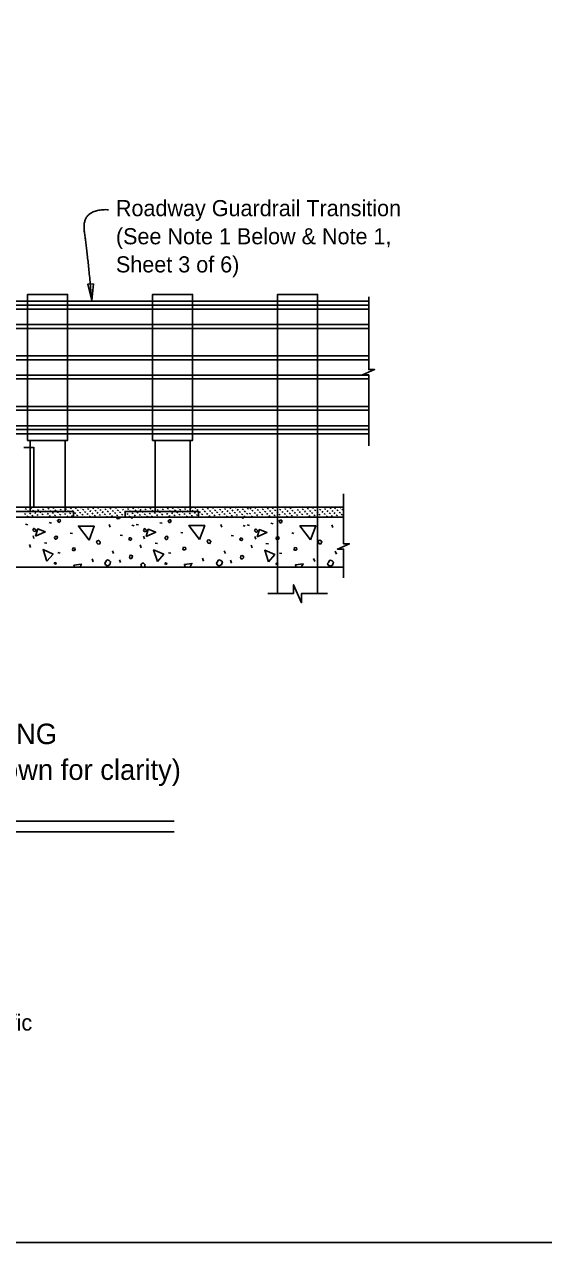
# Model space of a CAD drawing. Extents: x 1.5 to 68.7, y 0 to 31.1.
# Drawn here: x 14.15 to 20.65, y 1.78 to 17.03 of the extents above; entities that cross this region are included whole.
import ezdxf

# ---------------------------------------------------------------- set-up
doc = ezdxf.new("R2010")
doc.units = 0
for name, color, linetype in [('ActivePts-ConstElements', 7, 'Continuous'), ('Dimension', 7, 'Continuous'), ('Miscellaneous', 7, 'Continuous'), ('TrafBarrierConc', 7, 'Continuous')]:
    doc.layers.add(name, color=color, linetype=linetype)

msp = doc.modelspace()

# ---------------------------------------------------------------- linework, layer by layer
at = {"layer": 'ActivePts-ConstElements'}
msp.add_lwpolyline([(1.467, 28.183), (42.533, 28.183), (42.533, 1.783), (1.467, 1.783)], close=True, dxfattribs=at)
at = {"layer": 'Dimension'}
for p, q in [((12.038, 7.055), (16.027, 7.055)), ((12.038, 6.925), (16.027, 6.925))]:
    msp.add_line(p, q, dxfattribs=at)
msp.add_lwpolyline([(14.995, 13.57), (15.016, 13.78), (14.945, 13.775)], close=True, dxfattribs=at)
for points in [[(18.46, 11.755), (18.46, 12.641), (18.382, 12.641), (18.532, 12.708), (18.46, 12.708), (18.46, 13.616)], [(18.144, 10.101), (18.144, 10.462), (18.067, 10.462), (18.217, 10.528), (18.144, 10.528), (18.144, 11.154)], [(17.945, 9.906), (17.619, 9.906), (17.619, 9.789), (17.52, 10.014), (17.52, 9.906), (17.195, 9.906)]]:
    msp.add_lwpolyline(points, dxfattribs=at)
msp.add_open_spline([(15.206, 14.708), (14.861, 14.721), (14.944, 14.148), (14.995, 13.57)], degree=2, dxfattribs=at)
at = {"layer": 'Miscellaneous'}
for p, q in [((6.514, 13.565), (18.46, 13.565)), ((7.172, 13.512), (18.46, 13.512)), ((7.173, 13.464), (18.46, 13.464)), ((7.178, 13.271), (18.46, 13.271)), ((7.179, 13.223), (18.46, 13.223)), ((7.174, 12.831), (18.46, 12.831)), ((7.175, 12.879), (18.46, 12.879)), ((7.168, 12.59), (18.46, 12.59)), ((7.169, 12.638), (18.46, 12.638)), ((7.178, 12.198), (18.46, 12.198)), ((7.179, 12.246), (18.46, 12.246)), ((6.514, 11.904), (18.46, 11.904)), ((7.172, 11.957), (18.46, 11.957)), ((7.173, 12.005), (18.46, 12.005)), ((14.224, 10.932), (14.224, 11.821)), ((14.662, 10.932), (14.662, 11.821)), ((15.787, 10.932), (15.787, 11.821)), ((16.224, 10.932), (16.224, 11.821)), ((14.229, 10.963), (14.238, 10.977)), ((14.511, 10.968), (14.519, 10.982)), ((14.729, 10.965), (14.737, 10.979)), ((14.79, 10.967), (14.798, 10.981)), ((14.854, 10.975), (14.859, 10.985)), ((14.917, 10.983), (14.918, 10.985)), ((15.009, 10.963), (15.017, 10.977)), ((15.072, 10.971), (15.08, 10.985)), ((15.136, 10.98), (15.138, 10.985)), ((15.29, 10.968), (15.298, 10.982)), ((15.354, 10.976), (15.359, 10.985)), ((15.417, 10.984), (15.417, 10.985)), ((15.508, 10.965), (15.516, 10.979)), ((15.572, 10.973), (15.579, 10.985)), ((15.635, 10.981), (15.637, 10.985)), ((15.787, 10.97), (15.796, 10.984)), ((15.851, 10.978), (15.855, 10.985)), ((16.006, 10.967), (16.014, 10.981)), ((16.069, 10.975), (16.075, 10.985)), ((16.133, 10.983), (16.134, 10.985)), ((16.224, 10.963), (16.232, 10.977)), ((16.287, 10.971), (16.295, 10.985)), ((16.351, 10.98), (16.354, 10.985)), ((16.505, 10.968), (16.514, 10.982)), ((16.569, 10.976), (16.574, 10.985)), ((16.632, 10.984), (16.633, 10.985)), ((16.724, 10.965), (16.732, 10.979)), ((16.788, 10.973), (16.795, 10.984)), ((16.851, 10.981), (16.853, 10.984)), ((17.039, 10.97), (17.047, 10.984)), ((17.257, 10.967), (17.265, 10.981)), ((17.475, 10.963), (17.484, 10.977)), ((17.757, 10.968), (17.765, 10.982)), ((17.975, 10.965), (17.983, 10.979)), ((18.036, 10.967), (18.044, 10.981)), ((18.1, 10.975), (18.105, 10.985)), ((14.158, 10.892), (14.166, 10.906)), ((14.166, 10.955), (14.174, 10.969)), ((14.186, 10.864), (14.194, 10.878)), ((14.194, 10.928), (14.202, 10.942)), ((14.221, 10.9), (14.229, 10.914)), ((14.245, 10.859), (14.247, 10.862)), ((14.249, 10.872), (14.257, 10.886)), ((14.257, 10.936), (14.265, 10.95)), ((14.285, 10.908), (14.293, 10.922)), ((14.313, 10.88), (14.321, 10.894)), ((14.321, 10.944), (14.329, 10.958)), ((14.348, 10.916), (14.356, 10.93)), ((14.376, 10.888), (14.384, 10.902)), ((14.384, 10.952), (14.392, 10.966)), ((14.412, 10.924), (14.42, 10.938)), ((14.44, 10.896), (14.448, 10.91)), ((14.448, 10.96), (14.456, 10.974)), ((14.467, 10.869), (14.475, 10.883)), ((14.475, 10.932), (14.483, 10.946)), ((14.503, 10.905), (14.511, 10.919)), ((14.524, 10.859), (14.528, 10.867)), ((14.531, 10.877), (14.539, 10.891)), ((14.539, 10.94), (14.547, 10.954)), ((14.567, 10.913), (14.575, 10.927)), ((14.594, 10.885), (14.602, 10.899)), ((14.602, 10.948), (14.61, 10.962)), ((14.63, 10.921), (14.638, 10.935)), ((14.658, 10.893), (14.666, 10.907)), ((14.666, 10.957), (14.674, 10.971)), ((14.685, 10.865), (14.694, 10.879)), ((14.694, 10.929), (14.702, 10.943)), ((14.721, 10.901), (14.729, 10.915)), ((14.746, 10.867), (14.755, 10.881)), ((14.755, 10.931), (14.763, 10.945)), ((14.782, 10.903), (14.79, 10.917)), ((14.81, 10.876), (14.818, 10.89)), ((14.818, 10.939), (14.826, 10.953)), ((14.844, 10.86), (14.846, 10.862)), ((14.846, 10.911), (14.854, 10.925)), ((14.873, 10.884), (14.882, 10.898)), ((14.882, 10.947), (14.89, 10.961)), ((14.903, 10.86), (14.909, 10.87)), ((14.909, 10.919), (14.917, 10.933)), ((14.937, 10.892), (14.945, 10.906)), ((14.945, 10.955), (14.953, 10.969)), ((14.965, 10.864), (14.973, 10.878)), ((14.973, 10.928), (14.981, 10.942)), ((15, 10.9), (15.009, 10.914)), ((15.028, 10.872), (15.036, 10.886)), ((15.036, 10.936), (15.044, 10.95)), ((15.064, 10.908), (15.072, 10.922)), ((15.092, 10.88), (15.1, 10.894)), ((15.099, 10.856), (15.099, 10.856)), ((15.1, 10.944), (15.108, 10.958)), ((15.123, 10.86), (15.127, 10.867)), ((15.127, 10.916), (15.136, 10.93)), ((15.155, 10.888), (15.163, 10.902)), ((15.163, 10.952), (15.171, 10.966)), ((15.183, 10.861), (15.191, 10.875)), ((15.191, 10.924), (15.199, 10.938)), ((15.219, 10.896), (15.227, 10.91)), ((15.227, 10.96), (15.235, 10.974)), ((15.246, 10.869), (15.254, 10.883)), ((15.254, 10.932), (15.263, 10.946)), ((15.282, 10.905), (15.29, 10.919)), ((15.31, 10.877), (15.318, 10.891)), ((15.318, 10.94), (15.326, 10.954)), ((15.343, 10.86), (15.346, 10.863)), ((15.346, 10.913), (15.354, 10.927)), ((15.373, 10.885), (15.381, 10.899)), ((15.381, 10.948), (15.39, 10.962)), ((15.402, 10.86), (15.409, 10.871)), ((15.409, 10.921), (15.417, 10.935)), ((15.437, 10.893), (15.445, 10.907)), ((15.445, 10.957), (15.453, 10.971)), ((15.464, 10.865), (15.473, 10.879)), ((15.473, 10.929), (15.481, 10.943)), ((15.5, 10.901), (15.508, 10.915)), ((15.528, 10.874), (15.536, 10.888)), ((15.536, 10.937), (15.544, 10.951)), ((15.564, 10.909), (15.572, 10.923)), ((15.564, 10.86), (15.564, 10.86)), ((15.591, 10.882), (15.6, 10.896)), ((15.6, 10.945), (15.608, 10.959)), ((15.622, 10.86), (15.627, 10.868)), ((15.627, 10.917), (15.635, 10.931)), ((15.655, 10.89), (15.663, 10.904)), ((15.663, 10.953), (15.671, 10.967)), ((15.683, 10.862), (15.691, 10.876)), ((15.691, 10.926), (15.699, 10.94)), ((15.718, 10.898), (15.727, 10.912)), ((15.727, 10.961), (15.735, 10.975)), ((15.746, 10.87), (15.751, 10.879)), ((15.752, 10.934), (15.76, 10.948)), ((15.779, 10.907), (15.787, 10.921)), ((15.807, 10.879), (15.815, 10.893)), ((15.815, 10.942), (15.823, 10.956)), ((15.843, 10.915), (15.851, 10.929)), ((15.871, 10.887), (15.879, 10.901)), ((15.879, 10.951), (15.887, 10.965)), ((15.906, 10.923), (15.914, 10.937)), ((15.934, 10.895), (15.942, 10.909)), ((15.942, 10.959), (15.95, 10.973)), ((15.962, 10.867), (15.97, 10.881)), ((15.97, 10.931), (15.978, 10.945)), ((15.998, 10.903), (16.006, 10.917)), ((16.025, 10.876), (16.033, 10.89)), ((16.033, 10.939), (16.041, 10.953)), ((16.061, 10.911), (16.069, 10.925)), ((16.089, 10.884), (16.097, 10.898)), ((16.097, 10.947), (16.105, 10.961)), ((16.125, 10.919), (16.133, 10.933)), ((16.152, 10.892), (16.16, 10.906)), ((16.16, 10.955), (16.168, 10.969)), ((16.18, 10.864), (16.188, 10.878)), ((16.188, 10.928), (16.196, 10.942)), ((16.216, 10.9), (16.224, 10.914)), ((16.239, 10.86), (16.241, 10.862)), ((16.243, 10.872), (16.252, 10.886)), ((16.252, 10.936), (16.26, 10.95)), ((16.279, 10.908), (16.287, 10.922)), ((16.307, 10.88), (16.315, 10.894)), ((16.315, 10.944), (16.323, 10.958)), ((16.343, 10.916), (16.351, 10.93)), ((16.37, 10.888), (16.378, 10.902)), ((16.378, 10.952), (16.387, 10.966)), ((16.406, 10.924), (16.414, 10.938)), ((16.434, 10.896), (16.442, 10.91)), ((16.442, 10.96), (16.45, 10.974)), ((16.462, 10.869), (16.47, 10.883)), ((16.47, 10.932), (16.478, 10.946)), ((16.497, 10.905), (16.505, 10.919)), ((16.518, 10.86), (16.523, 10.867)), ((16.525, 10.877), (16.533, 10.891)), ((16.533, 10.94), (16.541, 10.954)), ((16.561, 10.913), (16.569, 10.927)), ((16.589, 10.885), (16.597, 10.899)), ((16.597, 10.948), (16.605, 10.962)), ((16.624, 10.921), (16.632, 10.935)), ((16.652, 10.893), (16.66, 10.907)), ((16.66, 10.957), (16.668, 10.971)), ((16.68, 10.865), (16.688, 10.879)), ((16.688, 10.929), (16.696, 10.943)), ((16.716, 10.901), (16.724, 10.915)), ((16.739, 10.859), (16.741, 10.863)), ((16.744, 10.873), (16.752, 10.887)), ((16.752, 10.937), (16.76, 10.951)), ((16.78, 10.909), (16.788, 10.923)), ((16.798, 10.859), (16.805, 10.871)), ((16.807, 10.882), (16.815, 10.896)), ((16.815, 10.945), (16.824, 10.959)), ((16.843, 10.917), (16.851, 10.931)), ((16.871, 10.89), (16.879, 10.904)), ((16.879, 10.953), (16.887, 10.967)), ((16.899, 10.862), (16.907, 10.876)), ((16.907, 10.925), (16.915, 10.939)), ((16.934, 10.898), (16.942, 10.912)), ((16.942, 10.961), (16.951, 10.975)), ((16.953, 10.855), (16.953, 10.855)), ((16.97, 10.898), (16.978, 10.912)), ((16.978, 10.961), (16.986, 10.975)), ((16.998, 10.87), (17.003, 10.879)), ((17.003, 10.934), (17.011, 10.948)), ((17.031, 10.907), (17.039, 10.921)), ((17.059, 10.879), (17.067, 10.893)), ((17.067, 10.942), (17.075, 10.956)), ((17.095, 10.915), (17.103, 10.929)), ((17.122, 10.887), (17.13, 10.901)), ((17.13, 10.951), (17.138, 10.964)), ((17.158, 10.923), (17.166, 10.937)), ((17.186, 10.895), (17.194, 10.909)), ((17.194, 10.959), (17.202, 10.973)), ((17.213, 10.867), (17.221, 10.881)), ((17.221, 10.931), (17.23, 10.945)), ((17.249, 10.903), (17.257, 10.917)), ((17.277, 10.876), (17.285, 10.89)), ((17.285, 10.939), (17.293, 10.953)), ((17.313, 10.911), (17.321, 10.925)), ((17.34, 10.884), (17.348, 10.898)), ((17.348, 10.947), (17.357, 10.961)), ((17.376, 10.919), (17.384, 10.933)), ((17.404, 10.892), (17.412, 10.906)), ((17.412, 10.955), (17.42, 10.969)), ((17.432, 10.864), (17.44, 10.878)), ((17.44, 10.928), (17.448, 10.942)), ((17.467, 10.9), (17.475, 10.914)), ((17.491, 10.859), (17.492, 10.862)), ((17.495, 10.872), (17.503, 10.886)), ((17.503, 10.936), (17.511, 10.95)), ((17.531, 10.908), (17.539, 10.922)), ((17.559, 10.88), (17.567, 10.894)), ((17.567, 10.944), (17.575, 10.958)), ((17.594, 10.916), (17.602, 10.93)), ((17.622, 10.888), (17.63, 10.902)), ((17.63, 10.952), (17.638, 10.966)), ((17.658, 10.924), (17.666, 10.938)), ((17.686, 10.896), (17.694, 10.91)), ((17.694, 10.96), (17.702, 10.974)), ((17.713, 10.869), (17.721, 10.883)), ((17.721, 10.932), (17.729, 10.946)), ((17.749, 10.905), (17.757, 10.919)), ((17.77, 10.859), (17.774, 10.867)), ((17.777, 10.877), (17.785, 10.891)), ((17.785, 10.94), (17.793, 10.954)), ((17.813, 10.913), (17.821, 10.927)), ((17.84, 10.885), (17.848, 10.899)), ((17.848, 10.948), (17.856, 10.962)), ((17.876, 10.921), (17.884, 10.935)), ((17.904, 10.893), (17.912, 10.907)), ((17.912, 10.957), (17.92, 10.971)), ((17.931, 10.865), (17.94, 10.879)), ((17.94, 10.929), (17.948, 10.943)), ((17.967, 10.901), (17.975, 10.915)), ((17.992, 10.867), (18.001, 10.881)), ((18.001, 10.931), (18.009, 10.945)), ((18.028, 10.903), (18.036, 10.917)), ((18.056, 10.876), (18.064, 10.89)), ((18.064, 10.939), (18.072, 10.953)), ((18.09, 10.86), (18.092, 10.862)), ((18.092, 10.911), (18.1, 10.925)), ((18.119, 10.884), (18.128, 10.898)), ((18.128, 10.947), (18.136, 10.961)), ((14.166, 10.773), (14.195, 10.766)), ((14.462, 10.792), (14.492, 10.787)), ((15.224, 10.734), (15.212, 10.768)), ((15.498, 10.761), (15.527, 10.754)), ((15.55, 10.77), (15.578, 10.763)), ((15.846, 10.789), (15.876, 10.784)), ((16.621, 10.734), (16.609, 10.768)), ((16.887, 10.756), (16.915, 10.749)), ((16.939, 10.765), (16.967, 10.758)), ((17.235, 10.784), (17.265, 10.779)), ((18.01, 10.73), (17.998, 10.763)), ((14.272, 10.592), (14.26, 10.626)), ((14.402, 10.538), (14.434, 10.534)), ((14.726, 10.66), (14.752, 10.655)), ((15.352, 10.635), (15.378, 10.63)), ((15.656, 10.589), (15.644, 10.622)), ((15.786, 10.534), (15.817, 10.531)), ((16.108, 10.668), (16.135, 10.663)), ((16.74, 10.631), (16.767, 10.625)), ((17.045, 10.584), (17.033, 10.618)), ((17.174, 10.53), (17.206, 10.526)), ((17.497, 10.664), (17.524, 10.658)), ((14.23, 10.483), (14.216, 10.518)), ((14.57, 10.419), (14.598, 10.412)), ((15.268, 10.404), (15.254, 10.439)), ((15.614, 10.479), (15.599, 10.514)), ((15.953, 10.416), (15.982, 10.409)), ((16.666, 10.404), (16.651, 10.439)), ((17.003, 10.475), (16.988, 10.51)), ((17.342, 10.411), (17.371, 10.404)), ((18.054, 10.399), (18.04, 10.434)), ((15.012, 10.303), (14.998, 10.338)), ((15.356, 10.292), (15.341, 10.327)), ((16.394, 10.311), (16.38, 10.346)), ((16.744, 10.287), (16.73, 10.323)), ((17.783, 10.307), (17.769, 10.342))]:
    msp.add_line(p, q, dxfattribs=at)
for points in [[(14.193, 11.821), (14.693, 11.821), (14.693, 13.648), (14.193, 13.648)], [(15.755, 11.821), (16.255, 11.821), (16.255, 13.648), (15.755, 13.648)], [(13.85, 10.859), (14.766, 10.859), (14.766, 10.932), (13.85, 10.932)], [(15.412, 10.859), (16.329, 10.859), (16.329, 10.932), (15.412, 10.932)]]:
    msp.add_lwpolyline(points, close=True, dxfattribs=at)
for points in [[(17.32, 9.906), (17.32, 13.648), (17.82, 13.648), (17.82, 9.906)], [(14.573, 10.805), (14.584, 10.794), (14.595, 10.801), (14.602, 10.812), (14.598, 10.829), (14.589, 10.831), (14.577, 10.829), (14.566, 10.819), (14.573, 10.805)], [(15.306, 10.856), (15.316, 10.84), (15.339, 10.842), (15.348, 10.851), (15.353, 10.856)], [(15.495, 10.846), (15.492, 10.856)], [(15.5, 10.856), (15.495, 10.846)], [(15.957, 10.801), (15.968, 10.791), (15.978, 10.798), (15.985, 10.808), (15.982, 10.826), (15.973, 10.828), (15.961, 10.826), (15.95, 10.815), (15.957, 10.801)], [(16.884, 10.842), (16.881, 10.852)], [(16.889, 10.852), (16.884, 10.842)], [(14.269, 10.685), (14.281, 10.683), (14.294, 10.688), (14.297, 10.699), (14.292, 10.708), (14.281, 10.715), (14.269, 10.72), (14.262, 10.706), (14.258, 10.696), (14.269, 10.685)], [(14.291, 10.621), (14.319, 10.713), (14.413, 10.676), (14.291, 10.621)], [(14.961, 10.573), (14.827, 10.75), (15.026, 10.748), (14.961, 10.573)], [(15.652, 10.681), (15.665, 10.68), (15.677, 10.685), (15.681, 10.696), (15.675, 10.704), (15.665, 10.712), (15.652, 10.717), (15.645, 10.703), (15.642, 10.692), (15.652, 10.681)], [(15.674, 10.617), (15.702, 10.709), (15.796, 10.672), (15.674, 10.617)], [(16.343, 10.581), (16.209, 10.758), (16.409, 10.756), (16.343, 10.581)], [(17.041, 10.677), (17.054, 10.675), (17.066, 10.681), (17.07, 10.691), (17.064, 10.7), (17.054, 10.707), (17.041, 10.712), (17.034, 10.698), (17.031, 10.688), (17.041, 10.677)], [(17.063, 10.613), (17.091, 10.705), (17.185, 10.668), (17.063, 10.613)], [(17.346, 10.797), (17.357, 10.786), (17.367, 10.793), (17.374, 10.804), (17.371, 10.822), (17.362, 10.823), (17.349, 10.822), (17.339, 10.811), (17.346, 10.797)], [(17.732, 10.577), (17.598, 10.754), (17.798, 10.752), (17.732, 10.577)], [(14.538, 10.585), (14.545, 10.585), (14.559, 10.593), (14.565, 10.608), (14.563, 10.617), (14.549, 10.624), (14.531, 10.614), (14.527, 10.603), (14.531, 10.593), (14.538, 10.585)], [(15.06, 10.541), (15.069, 10.525), (15.09, 10.522), (15.099, 10.538), (15.102, 10.552), (15.093, 10.561), (15.078, 10.57), (15.062, 10.564), (15.056, 10.548), (15.06, 10.541)], [(15.459, 10.577), (15.479, 10.571), (15.491, 10.58), (15.493, 10.593), (15.489, 10.596), (15.475, 10.603), (15.463, 10.601), (15.461, 10.589), (15.459, 10.577)], [(15.922, 10.582), (15.929, 10.582), (15.943, 10.589), (15.948, 10.605), (15.946, 10.614), (15.932, 10.621), (15.915, 10.61), (15.911, 10.6), (15.915, 10.589), (15.922, 10.582)], [(16.442, 10.55), (16.451, 10.534), (16.472, 10.53), (16.481, 10.546), (16.485, 10.56), (16.476, 10.569), (16.46, 10.578), (16.444, 10.573), (16.439, 10.557), (16.442, 10.55)], [(16.848, 10.572), (16.868, 10.567), (16.88, 10.576), (16.882, 10.588), (16.878, 10.592), (16.864, 10.599), (16.852, 10.597), (16.85, 10.585), (16.848, 10.572)], [(17.311, 10.578), (17.318, 10.578), (17.332, 10.585), (17.337, 10.601), (17.335, 10.609), (17.321, 10.617), (17.303, 10.606), (17.3, 10.595), (17.303, 10.585), (17.311, 10.578)], [(17.831, 10.545), (17.84, 10.529), (17.861, 10.526), (17.87, 10.542), (17.874, 10.556), (17.865, 10.565), (17.849, 10.574), (17.833, 10.568), (17.828, 10.552), (17.831, 10.545)], [(14.433, 10.308), (14.386, 10.454), (14.511, 10.399), (14.433, 10.308)], [(14.758, 10.444), (14.779, 10.444), (14.789, 10.455), (14.784, 10.474), (14.761, 10.476), (14.758, 10.465), (14.752, 10.457), (14.758, 10.444), (14.754, 10.448)], [(15.465, 10.359), (15.474, 10.343), (15.493, 10.345), (15.502, 10.357), (15.504, 10.377), (15.492, 10.382), (15.483, 10.384), (15.472, 10.38), (15.469, 10.377), (15.465, 10.359)], [(15.817, 10.304), (15.769, 10.451), (15.895, 10.396), (15.817, 10.304)], [(16.14, 10.452), (16.161, 10.452), (16.172, 10.463), (16.166, 10.482), (16.143, 10.484), (16.14, 10.474), (16.135, 10.465), (16.14, 10.452), (16.136, 10.456)], [(16.854, 10.354), (16.863, 10.339), (16.882, 10.34), (16.891, 10.353), (16.893, 10.372), (16.881, 10.377), (16.872, 10.379), (16.861, 10.376), (16.858, 10.372), (16.854, 10.354)], [(17.206, 10.3), (17.158, 10.446), (17.284, 10.392), (17.206, 10.3)], [(17.529, 10.448), (17.55, 10.448), (17.561, 10.459), (17.555, 10.478), (17.532, 10.48), (17.529, 10.469), (17.524, 10.46), (17.529, 10.448), (17.525, 10.452)], [(14.532, 10.272), (14.552, 10.281), (14.545, 10.288), (14.532, 10.293), (14.527, 10.281), (14.532, 10.272)], [(14.781, 10.231), (14.772, 10.26), (14.865, 10.273), (14.844, 10.231)], [(15.166, 10.266), (15.189, 10.253), (15.219, 10.266), (15.231, 10.303), (15.214, 10.32), (15.191, 10.326), (15.18, 10.319), (15.168, 10.299), (15.159, 10.283), (15.166, 10.266)], [(15.642, 10.231), (15.652, 10.239), (15.66, 10.249), (15.66, 10.27), (15.644, 10.286), (15.624, 10.285), (15.615, 10.276), (15.61, 10.26)], [(15.61, 10.26), (15.621, 10.239), (15.633, 10.231)], [(15.916, 10.269), (15.935, 10.278), (15.928, 10.285), (15.916, 10.29), (15.911, 10.278), (15.916, 10.269)], [(16.164, 10.239), (16.154, 10.269), (16.248, 10.281), (16.226, 10.239)], [(16.563, 10.266), (16.586, 10.253), (16.616, 10.266), (16.628, 10.303), (16.611, 10.32), (16.588, 10.326), (16.577, 10.319), (16.565, 10.299), (16.556, 10.283), (16.563, 10.266)], [(17.305, 10.264), (17.324, 10.273), (17.317, 10.28), (17.305, 10.286), (17.3, 10.273), (17.305, 10.264)], [(17.552, 10.235), (17.543, 10.264), (17.637, 10.277), (17.615, 10.235)], [(17.952, 10.261), (17.975, 10.249), (18.005, 10.261), (18.017, 10.298), (18, 10.316), (17.977, 10.321), (17.966, 10.314), (17.954, 10.295), (17.945, 10.279), (17.952, 10.261)]]:
    msp.add_lwpolyline(points, dxfattribs=at)
at = {"layer": 'TrafBarrierConc'}
for p, q in [((14.146, 11.734), (14.271, 11.734)), ((14.271, 11.735), (14.271, 10.985)), ((3.872, 10.984), (18.144, 10.984)), ((11.816, 10.859), (18.144, 10.859)), ((9.092, 10.234), (18.144, 10.234))]:
    msp.add_line(p, q, dxfattribs=at)

# ---------------------------------------------------------------- texts
at = {"layer": 'Dimension'}
for s, height, p in [('Roadway Guardrail Transition', 0.2016, (15.297, 14.627)), ('(See Note 1 Below & Note 1,', 0.2016, (15.297, 14.275)), ('Sheet 3 of 6)', 0.2016, (15.297, 13.923)), ('PARTIAL ELEVATION OF INSIDE FACE OF RAILING', 0.256, (6.267, 8.021)), ('(Existing Wing Post, Railing Reinforcing and Expansion Dowel Assemblies not shown for clarity)', 0.256, (1.573, 7.573)), ('1. See Roadway Plans for limiting station of Roadway Guardrail Transition or other site specific', 0.2016, (2.937, 4.436))]:
    msp.add_text(s, height=height, dxfattribs=at).set_placement(p)

doc.saveas('drawing.dxf')
